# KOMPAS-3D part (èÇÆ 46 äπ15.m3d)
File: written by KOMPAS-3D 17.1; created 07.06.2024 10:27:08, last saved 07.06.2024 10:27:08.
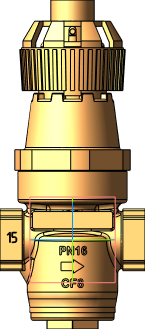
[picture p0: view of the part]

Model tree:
1. Операция без истории:1  (labels: Сталь 20  ГОСТ 1050-2013)

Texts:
  ООО АДЛ Групп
